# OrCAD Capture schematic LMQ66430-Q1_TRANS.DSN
size C; title: LMQ66430-Q1 PSPICE TRANSIENT SIMULATION; rev: A; note: DATASHEET #SNVSBV1
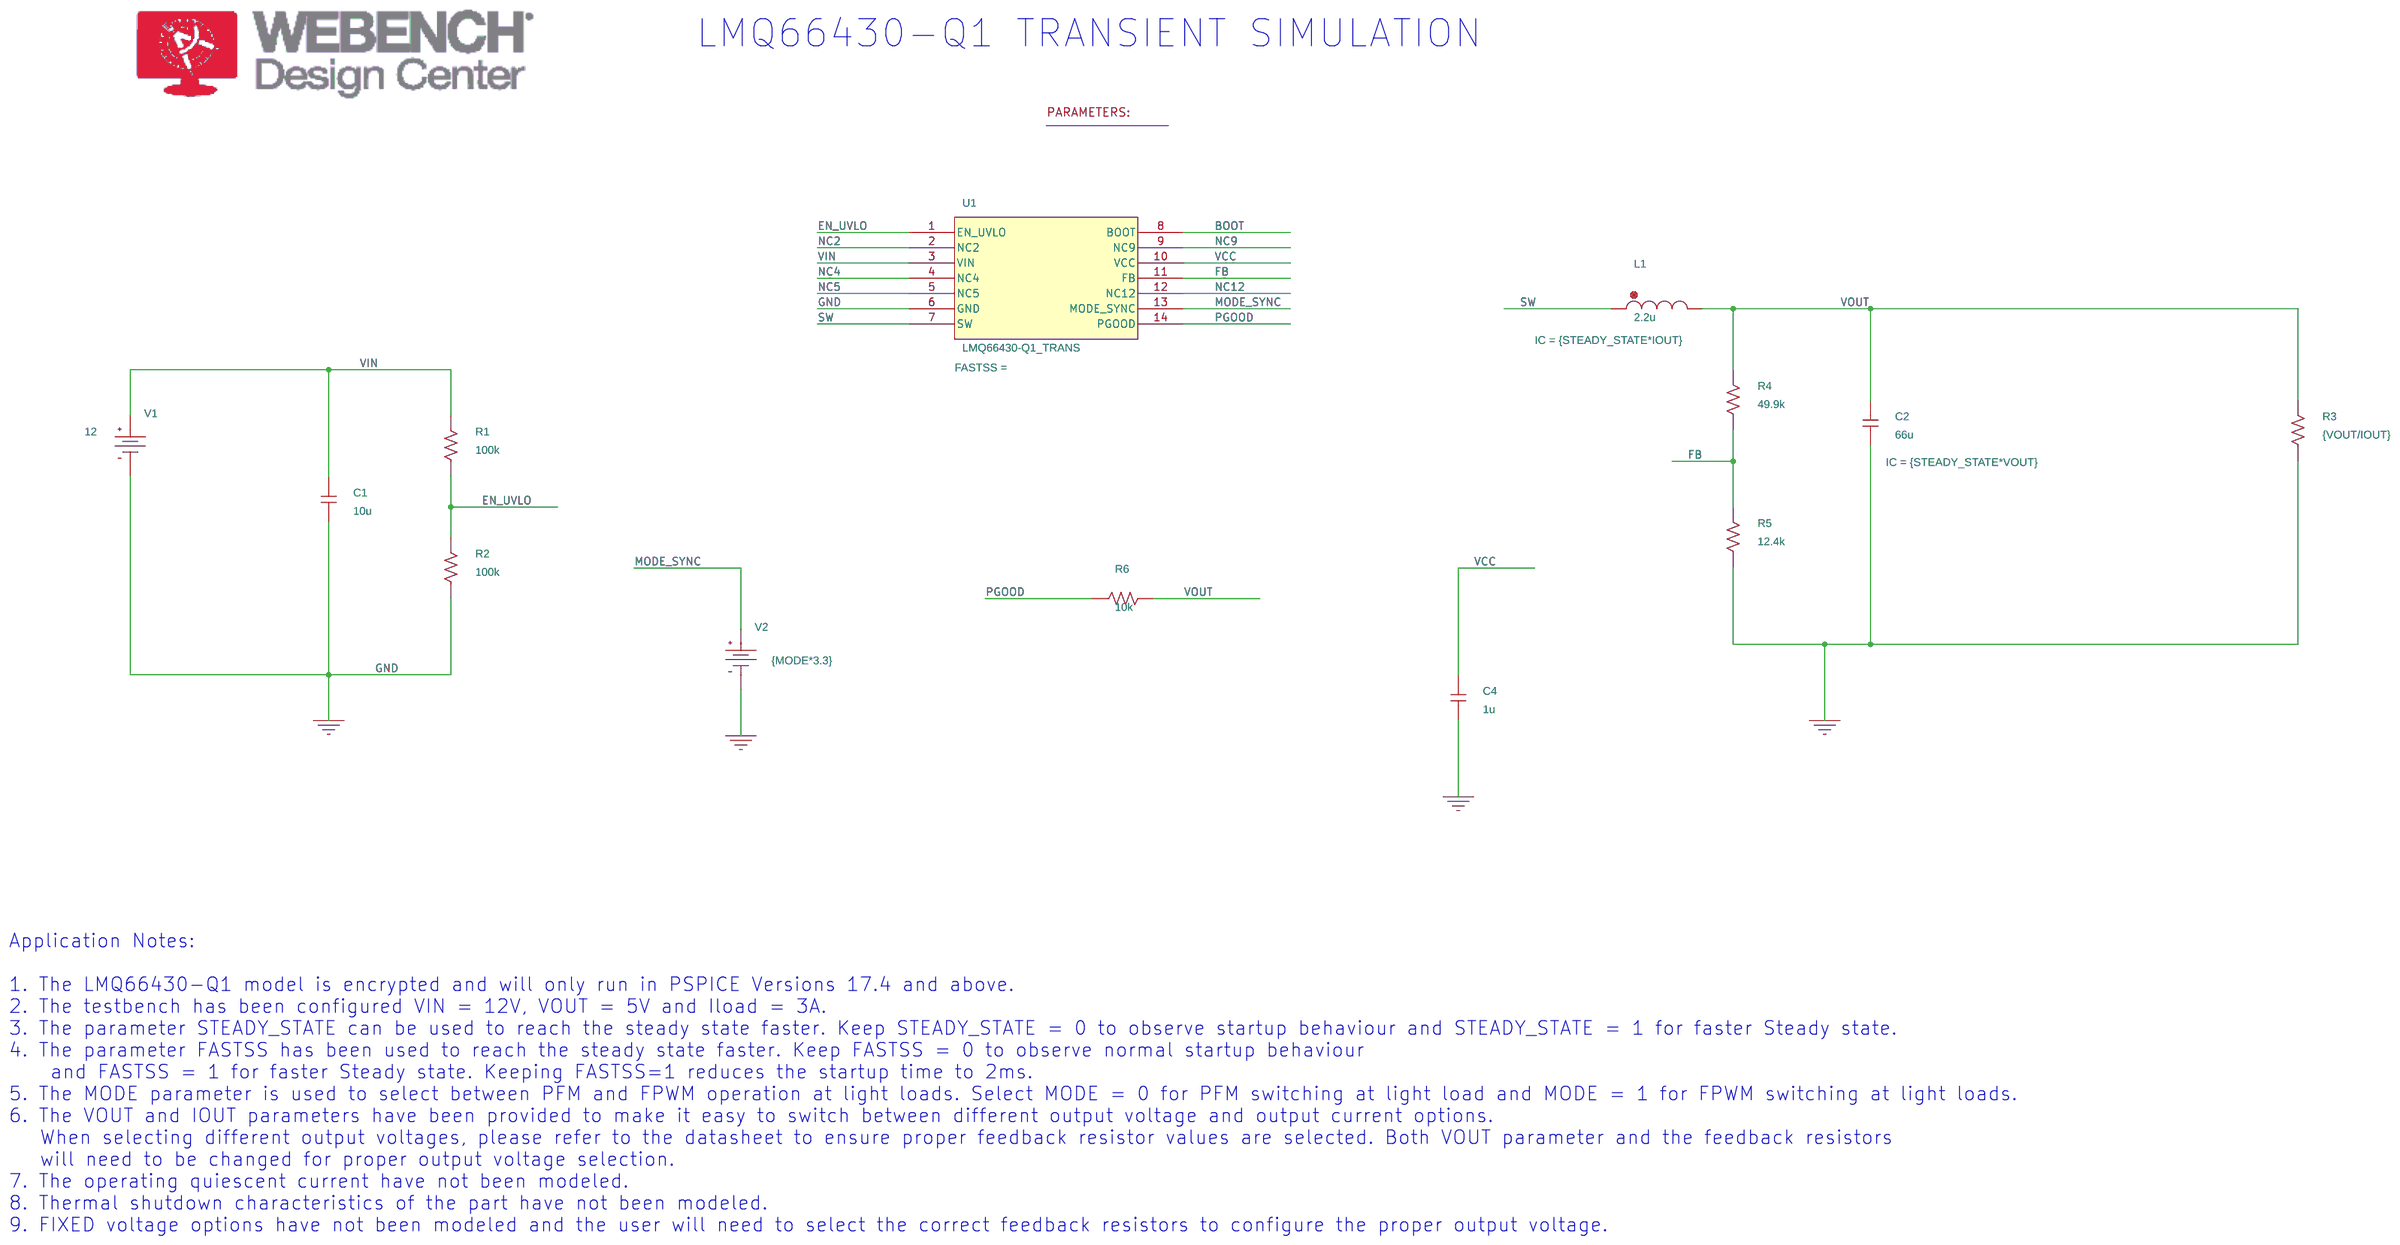
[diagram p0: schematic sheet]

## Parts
1  PARAM
C1  10u  [cap196]
C2  66u  [cap196]
C4  1u  [cap196]
L1  2.2u  [DISC350x175LS200x100034]
R1  100k  [AXRC05]
R2  100k  [AXRC05]
R3  {VOUT/IOUT}  [AXRC05]
R4  49.9k  [AXRC05]
R5  12.4k  [AXRC05]
R6  10k  [AXRC05]
U1  LMQ66430-Q1_TRANS
V1  VDC
V2  VDC

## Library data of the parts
1 = PARAM: IOUT: 3; MODE: 0; STEADY_STATE: 0; VOUT: 5
C1 C4 = C
C2 = C: IC: {STEADY_STATE*VOUT}
L1 = L: IC: {STEADY_STATE*IOUT}
R1-R6 = R
U1 = LMQ66430-Q1_TRANS: STEADY_STATE: 0
V1 = VDC: DC: 12
V2 = VDC: DC: {MODE*3.3}

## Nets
VCC: C4.2 U1.10(VCC)
VIN: C1.2 R1.2 U1.3(VIN) V1.0(+)
0: C1.1 C2.1 C4.1 R2.1 R3.1 R5.1 U1.6(GND) V1.1(-) V2.1(-)
BOOT: U1.8(BOOT)
EN_UVLO: R1.1 R2.2 U1.1(EN_UVLO)
FB: R4.1 R5.2 U1.11(FB)
MODE_SYNC: U1.13(MODE_SYNC) V2.0(+)
NC2: U1.2(NC2)
NC4: U1.4(NC4)
NC5: U1.5(NC5)
NC9: U1.9(NC9)
NC12: U1.12(NC12)
PGOOD: R6.1 U1.14(PGOOD)
SW: L1.1 U1.7(SW)
VOUT: C2.2 L1.2 R3.2 R4.2 R6.2

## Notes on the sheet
- LMQ66430-Q1 TRANSIENT SIMULATION
- Application Notes:
  1. The LMQ66430-Q1 model is encrypted and will only run in PSPICE Versions 17.4 and above.
  2. The testbench has been configured VIN = 12V, VOUT = 5V and Iload = 3A.
  3. The parameter STEADY_STATE can be used to reach the steady state faster. Keep STEADY_STATE = 0 to observe startup behaviour and STEADY_STATE = 1 for faster Steady state.
  4. The parameter FASTSS has been used to reach the steady state faster. Keep FASTSS = 0 to observe normal startup behaviour
      and FASTSS = 1 for faster Steady state. Keeping FASTSS=1 reduces the startup time to 2ms.
  5. The MODE parameter is used to select between PFM and FPWM operation at light loads. Select MODE = 0 for PFM switching at light load and MODE = 1 for FPWM switching at light loads.
  6. The VOUT and IOUT parameters have been provided to make it easy to switch between different output voltage and output current options.
     When selecting different output voltages, please refer to the datasheet to ensure proper feedback resistor values are selected. Both VOUT parameter and the feedback resistors
     will need to be changed for proper output voltage selection.
  7. The operating quiescent current have not been modeled.
  8. Thermal shutdown characteristics of the part have not been modeled.
  9. FIXED voltage options have not been modeled and the user will need to select the correct feedback resistors to configure the proper output voltage.
